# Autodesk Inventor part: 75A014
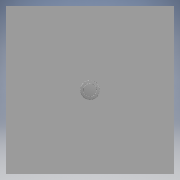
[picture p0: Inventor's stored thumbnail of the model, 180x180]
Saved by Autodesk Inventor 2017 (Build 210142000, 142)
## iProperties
Created: 2021-10
Part Number: 75A014
Material: Generico
Document SubType Name: Modeling
Designer: PIZZERA
Density: 1 g/cm^3
Appearance: Default
Author: PIZZERA
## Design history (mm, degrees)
feature "Base1"
feature "Base2"
feature "Base3"
feature "Base4"
feature "Base5"
feature "Base6"
node "Solido13"
node "Solido7"
node "Solido8"
node "Solido9"
node "Solido10"
node "Solido11"
node "Solido12"
